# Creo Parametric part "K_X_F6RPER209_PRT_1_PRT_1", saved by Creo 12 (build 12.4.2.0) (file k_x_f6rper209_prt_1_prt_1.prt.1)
Units: Custom; MM, KILOGRAM, SECS

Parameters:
  PTC_WM_ITERATION = "0"
  PTC_WM_VERSION = "-.0"
  PTC_WM_LIFECYCLE_STATE = "In Work"
  PTC_WM_LIFECYCLE = "MO_CADDocument"
  PTC_WM_CREATED_BY = "Maximilian Roepper (Z0017RMS: MO)"
  PTC_WM_CREATED_ON = "18-Sep-26 11:36:42 AM"
  PTC_WM_MODIFIED_BY = "Maximilian Roepper (Z0017RMS: MO)"
  PTC_WM_MODIFIED_ON = "18-Sep-26 11:36:46 AM"
  PDMLINKNUMBER = "PDM000071455026"
  PTC_WM_NAME = "k_x_f6rper209_prt_1_prt_1.prt"
  PTC_WM_NUMBER = "PDM000071455026"

Other parameters: WEIGHT, WEIGHT_FACTOR, WEIGHT_ADD, _MASS_TEMP, _DIFF_TEMP, MC_ERRORS, SUPPLIER

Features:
  1. coordinate system
  2. datum plane "PRT_YZ"
  3. datum plane "PRT_XY"
  4. datum plane "PRT_XZ"
  5. coordinate system
  6. datum axis
  7. datum axis
  8. datum axis
  9. coordinate system
  10. imported feature
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
Other named items: PRT, SIEMENS_MO, DRW_VIEW_ORG, PRT_X, PRT_Y, PRT_Z, CS0, ROUGH_GROB

Layers: 00_STD_CSYS-KSYS, 01_STD_PLANES-EBENEN, 02_STD_AXES-ACHSEN, 03_STD_CSYS-KSYS, 24_IMPORT_FEAT-IMPORT_KE

Surfaces: 7 plane, 6 tabulated cylinder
